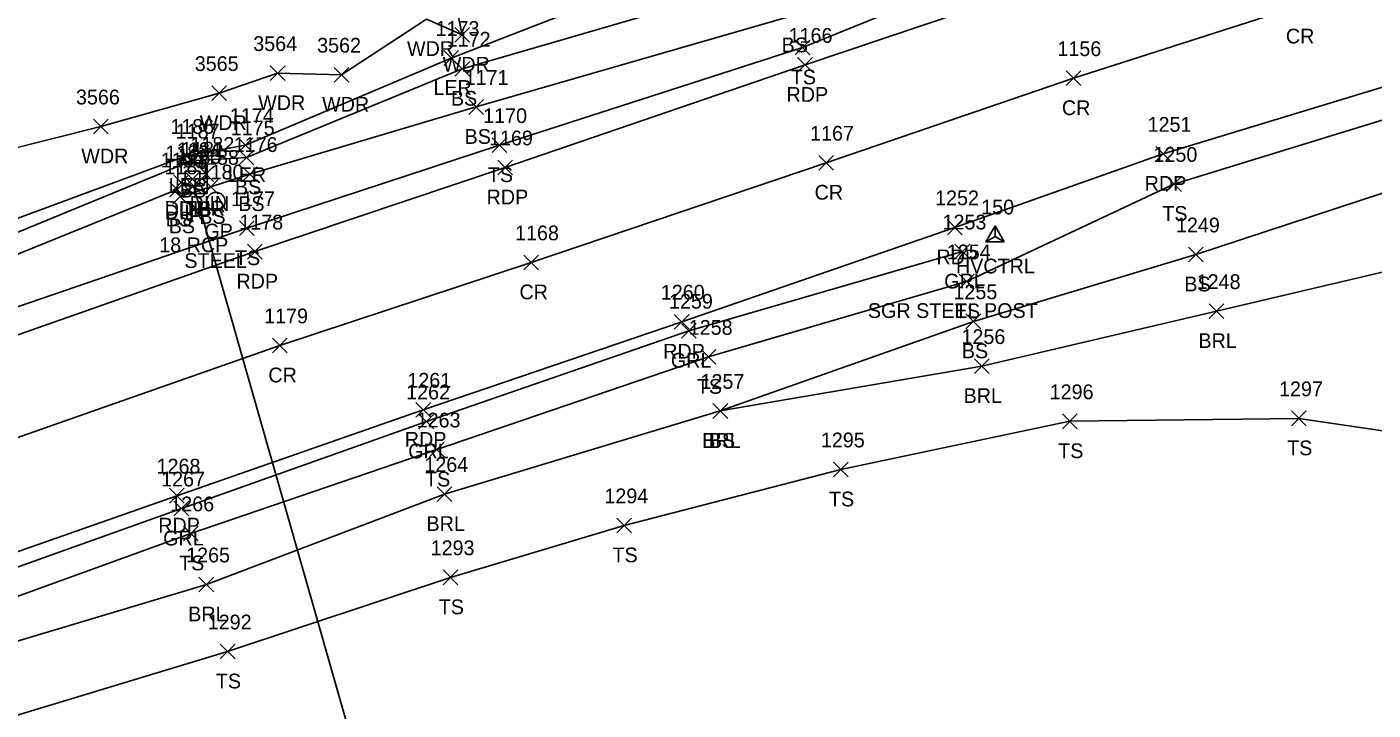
# Model space of a CAD drawing. Extents: x 1599569 to 1610055, y 642560 to 647860.
# Drawn here: x 1602081.3 to 1602263.8, y 647397.5 to 647490.2 of the extents above; entities that cross this region are included whole.
import ezdxf

# ---------------------------------------------------------------- set-up
doc = ezdxf.new("R2010")
doc.units = 0
for name, color, linetype in [('C_A', 7, 'Continuous'), ('C_I', 7, 'Continuous'), ('CPSM', 7, 'Continuous'), ('D_A', 7, 'Continuous'), ('D_C', 7, 'Continuous'), ('D_I', 7, 'Continuous'), ('D_TIC', 7, 'Continuous'), ('DCP', 7, 'Continuous'), ('DS', 7, 'Continuous'), ('L_A', 7, 'Continuous'), ('L_I', 7, 'Continuous'), ('L_TIC', 7, 'Continuous'), ('LABL', 7, 'Continuous'), ('LARO', 7, 'Continuous'), ('LAWA', 7, 'Continuous'), ('LELB', 7, 'Continuous'), ('P_A', 7, 'Continuous'), ('P_I', 7, 'Continuous'), ('P_TIC', 7, 'Continuous'), ('PET', 7, 'Continuous'), ('PRC', 7, 'Continuous'), ('R_A', 7, 'Continuous'), ('R_C', 7, 'Continuous'), ('R_I', 7, 'Continuous'), ('R_TIC', 7, 'Continuous'), ('RGP', 7, 'Continuous'), ('RGR', 7, 'Continuous')]:
    doc.layers.add(name, color=color, linetype=linetype)

msp = doc.modelspace()

# ---------------------------------------------------------------- linework, layer by layer
at = {"layer": 'CPSM'}
for p, q in [((1602211.32, 647461.02), (1602212.57, 647463.19)), ((1602213.82, 647461.02), (1602212.57, 647463.19)), ((1602212.57, 647461.74), (1602212.57, 647463.19)), ((1602211.32, 647461.02), (1602212.57, 647461.74)), ((1602211.32, 647461.02), (1602213.82, 647461.02)), ((1602212.57, 647461.74), (1602212.57, 647461.74)), ((1602212.57, 647461.74), (1602213.82, 647461.02))]:
    msp.add_line(p, q, dxfattribs=at)
at = {"layer": 'D_TIC'}
for points in [[(1602104.56, 647469.22), (1602106.56, 647471.22)], [(1602106.56, 647469.22), (1602104.56, 647471.22)], [(1602101.16, 647468.07), (1602103.16, 647470.07)], [(1602103.16, 647468.07), (1602101.16, 647470.07)], [(1602102.72, 647468.51), (1602104.72, 647470.51)], [(1602104.72, 647468.51), (1602102.72, 647470.51)], [(1602102.84, 647467.61), (1602104.84, 647469.61)], [(1602104.84, 647467.61), (1602102.84, 647469.61)]]:
    msp.add_lwpolyline(points, dxfattribs=at)
at = {"layer": 'DCP'}
msp.add_lwpolyline([(1602103.84, 647468.61), (1602127.27, 647386.57)], dxfattribs=at)
at = {"layer": 'DS'}
for p, q in [((1602101.7, 647471.59), (1602105.7, 647471.59)), ((1602101.7, 647467.59), (1602101.71, 647471.59)), ((1602105.7, 647471.59), (1602105.7, 647467.59)), ((1602102.7, 647470.59), (1602104.7, 647470.59)), ((1602102.7, 647468.59), (1602102.7, 647470.59)), ((1602103.7, 647469.6), (1602103.7, 647469.6)), ((1602104.7, 647470.59), (1602104.7, 647468.59)), ((1602105.7, 647467.59), (1602101.7, 647467.59)), ((1602104.7, 647468.59), (1602102.7, 647468.59)), ((1602104.2, 647467.59), (1602104.7, 647467.59))]:
    msp.add_line(p, q, dxfattribs=at)
at = {"layer": 'L_TIC'}
for points in [[(1602139.29, 647488.09), (1602141.29, 647490.09)], [(1602141.29, 647488.09), (1602139.29, 647490.09)], [(1602185.45, 647486.37), (1602187.45, 647488.37)], [(1602187.45, 647486.37), (1602185.45, 647488.37)], [(1602137.81, 647484.94), (1602139.81, 647486.94)], [(1602139.81, 647484.94), (1602137.81, 647486.94)], [(1602114.26, 647482.89), (1602116.26, 647484.89)], [(1602116.26, 647482.89), (1602114.26, 647484.89)], [(1602122.93, 647482.67), (1602124.93, 647484.67)], [(1602124.93, 647482.67), (1602122.93, 647484.67)], [(1602139.31, 647483.48), (1602141.31, 647485.48)], [(1602141.31, 647483.48), (1602139.31, 647485.48)], [(1602106.33, 647480.18), (1602108.33, 647482.18)], [(1602108.33, 647480.18), (1602106.33, 647482.18)], [(1602141.18, 647478.3), (1602143.18, 647480.3)], [(1602143.18, 647478.3), (1602141.18, 647480.3)], [(1602090.27, 647475.65), (1602092.27, 647477.65)], [(1602092.27, 647475.65), (1602090.27, 647477.65)], [(1602109.91, 647473.13), (1602111.91, 647475.13)], [(1602111.91, 647473.13), (1602109.91, 647475.13)], [(1602144.36, 647473.12), (1602146.36, 647475.12)], [(1602146.36, 647473.12), (1602144.36, 647475.12)], [(1602101.89, 647471.66), (1602103.89, 647473.66)], [(1602103.89, 647471.66), (1602101.89, 647473.66)], [(1602102.56, 647471.02), (1602104.56, 647473.02)], [(1602104.56, 647471.02), (1602102.56, 647473.02)], [(1602110.03, 647471.46), (1602112.03, 647473.46)], [(1602112.03, 647471.46), (1602110.03, 647473.46)], [(1602110.48, 647469.2), (1602112.48, 647471.2)], [(1602112.48, 647469.2), (1602110.48, 647471.2)], [(1602105.19, 647467.46), (1602107.19, 647469.46)], [(1602107.19, 647467.46), (1602105.19, 647469.46)], [(1602235.83, 647467.86), (1602237.83, 647469.86)], [(1602237.83, 647467.86), (1602235.83, 647469.86)], [(1602100.62, 647467.1), (1602102.62, 647469.1)], [(1602102.62, 647467.1), (1602100.62, 647469.1)], [(1602101.05, 647466.18), (1602103.05, 647468.18)], [(1602103.05, 647466.18), (1602101.05, 647468.18)], [(1602110.07, 647461.86), (1602112.07, 647463.86)], [(1602112.07, 647461.86), (1602110.07, 647463.86)], [(1602238.8, 647458.3), (1602240.8, 647460.3)], [(1602240.8, 647458.3), (1602238.8, 647460.3)], [(1602207.71, 647454.65), (1602209.71, 647456.65)], [(1602209.71, 647454.65), (1602207.71, 647456.65)], [(1602208.62, 647449.24), (1602210.62, 647451.24)], [(1602210.62, 647449.24), (1602208.62, 647451.24)], [(1602241.61, 647450.62), (1602243.61, 647452.62)], [(1602243.61, 647450.62), (1602241.61, 647452.62)], [(1602172.71, 647444.42), (1602174.71, 647446.42)], [(1602174.71, 647444.42), (1602172.71, 647446.42)], [(1602209.76, 647443.17), (1602211.76, 647445.17)], [(1602211.76, 647443.17), (1602209.76, 647445.17)], [(1602174.3, 647437.09), (1602176.3, 647439.09)], [(1602176.3, 647437.09), (1602174.3, 647439.09)], [(1602174.3, 647437.09), (1602176.3, 647439.09)], [(1602176.3, 647437.09), (1602174.3, 647439.09)], [(1602221.72, 647435.69), (1602223.72, 647437.69)], [(1602223.72, 647435.69), (1602221.72, 647437.69)], [(1602252.77, 647436.09), (1602254.77, 647438.09)], [(1602254.77, 647436.09), (1602252.77, 647438.09)], [(1602135.85, 647431.86), (1602137.85, 647433.86)], [(1602137.85, 647431.86), (1602135.85, 647433.86)], [(1602190.63, 647429.16), (1602192.63, 647431.16)], [(1602192.63, 647429.16), (1602190.63, 647431.16)], [(1602136.9, 647425.83), (1602138.9, 647427.83)], [(1602138.9, 647425.83), (1602136.9, 647427.83)], [(1602161.27, 647421.58), (1602163.27, 647423.58)], [(1602163.27, 647421.58), (1602161.27, 647423.58)], [(1602102.5, 647420.49), (1602104.5, 647422.49)], [(1602104.5, 647420.49), (1602102.5, 647422.49)], [(1602137.7, 647414.54), (1602139.7, 647416.54)], [(1602139.7, 647414.54), (1602137.7, 647416.54)], [(1602104.59, 647413.57), (1602106.59, 647415.57)], [(1602106.59, 647413.57), (1602104.59, 647415.57)], [(1602107.48, 647404.48), (1602109.48, 647406.48)], [(1602109.48, 647404.48), (1602107.48, 647406.48)]]:
    msp.add_lwpolyline(points, dxfattribs=at)
at = {"layer": 'LABL'}
msp.add_lwpolyline([(1602538.93, 647499.63), (1602515.77, 647504.47), (1602496.79, 647503.69), (1602468.13, 647504.07), (1602437.38, 647499.25), (1602407.68, 647491.96), (1602380.84, 647484.75), (1602352.64, 647480.69), (1602316.1, 647467.92), (1602276.24, 647459.53), (1602242.61, 647451.62), (1602210.76, 647444.17), (1602175.3, 647438.09), (1602137.9, 647426.83), (1602105.59, 647414.57), (1602070.4, 647404.05), (1602026.56, 647383.89), (1602007.33, 647369.55), (1602002.68, 647344.03), (1602051.38, 647339.86)], dxfattribs=at)
at = {"layer": 'LARO'}
msp.add_lwpolyline([(1602281.17, 647528.1), (1602249.28, 647518.68), (1602215.29, 647506.81), (1602182.96, 647503.09), (1602138.81, 647485.94), (1602110.91, 647474.13), (1602102.89, 647472.66), (1602065.84, 647459), (1602030.57, 647446.06), (1601996.63, 647434.93), (1601966.44, 647449.06), (1601954.75, 647432.61), (1601939.14, 647421.32), (1601907.5, 647403.47), (1601898.14, 647399.78), (1601888.11, 647399.67), (1601874.07, 647394.79), (1601848.49, 647386.96)], dxfattribs=at)
at = {"layer": 'LAWA'}
msp.add_lwpolyline([(1602267.89, 647531.91), (1602252.89, 647527.89), (1602245.34, 647522.06), (1602238.82, 647521.29), (1602231.93, 647518.02), (1602223.42, 647517.25), (1602221.44, 647514.34), (1602210.26, 647512.11), (1602187.69, 647505.07), (1602172.23, 647505.3), (1602151.88, 647506.59), (1602137.86, 647500.8), (1602140.29, 647489.09), (1602135.45, 647491.22), (1602123.93, 647483.67), (1602115.26, 647483.89), (1602107.33, 647481.18), (1602091.27, 647476.65), (1602071.28, 647471.64)], dxfattribs=at)
at = {"layer": 'LELB'}
for points in [[(1602281.75, 647527.04), (1602249.8, 647516.84), (1602215.67, 647505.92), (1602184.38, 647497.32), (1602140.31, 647484.48), (1602111.03, 647472.46), (1602103.56, 647472.02), (1602066.93, 647456.96), (1602030.71, 647444.95), (1601997.32, 647432.85), (1601974.14, 647429.14), (1601941.15, 647416.78), (1601908.35, 647402.2), (1601898.71, 647398.5), (1601889.19, 647398.4), (1601875.8, 647390.82), (1601849.76, 647382.4), (1601821.01, 647371.25), (1601793.34, 647364.77), (1601777.94, 647362.34), (1601752.2, 647359.53), (1601736.48, 647357.95), (1601705.98, 647345.02)], [(1602280.55, 647523.47), (1602249.62, 647512.84), (1602216.53, 647503.11), (1602185.17, 647491.71), (1602142.18, 647479.3), (1602111.48, 647470.2), (1602106.19, 647468.46), (1602102.05, 647467.18), (1602101.62, 647468.1), (1602067.36, 647454.23), (1602033.18, 647442.57), (1601998.29, 647429.71), (1601975.48, 647422.42), (1601942.86, 647410.81), (1601909.09, 647400.02), (1601898.83, 647395.63), (1601887.98, 647393.87), (1601875.49, 647387.75), (1601851.11, 647380.46), (1601821.5, 647369.32), (1601787.55, 647360.24), (1601760.01, 647349.17)], [(1602281.6, 647518.52), (1602249.84, 647509.15), (1602217.8, 647500.07), (1602186.45, 647487.37), (1602145.36, 647474.12), (1602111.07, 647462.86), (1602069.25, 647448.56), (1602037.69, 647438.14), (1601999.72, 647424.13), (1601976.97, 647416.76)], [(1602437.38, 647499.25), (1602407.74, 647500.37), (1602379.76, 647494.45), (1602350.6, 647487.83), (1602312.09, 647479.12), (1602274.73, 647470.77), (1602239.8, 647459.3), (1602209.62, 647450.24), (1602175.3, 647438.09)], [(1601875.37, 647298.23), (1601899.27, 647311.46), (1601933.4, 647328.44), (1601966.96, 647349.6), (1601991.6, 647361.72), (1602007.33, 647369.55), (1602053.05, 647388.73), (1602108.48, 647405.48), (1602138.7, 647415.54), (1602162.27, 647422.58), (1602191.63, 647430.16), (1602222.72, 647436.69), (1602253.77, 647437.09), (1602274.71, 647434), (1602308.64, 647432.46), (1602335.54, 647436.29), (1602372.31, 647451.76), (1602413.17, 647464.59), (1602450.85, 647476.95), (1602485.79, 647485.59)], [(1602272.83, 647479.89), (1602236.83, 647468.86), (1602208.71, 647455.65), (1602173.71, 647445.42), (1602136.85, 647432.86), (1602103.5, 647421.49), (1602068.54, 647408.84), (1602020.23, 647391.97), (1601979.79, 647378.49), (1601945.53, 647366.37), (1601912.4, 647353.37), (1601880.28, 647341.06), (1601842.54, 647327.65), (1601807.18, 647318.11)]]:
    msp.add_lwpolyline(points, dxfattribs=at)
at = {"layer": 'P_TIC'}
for points in [[(1602185.79, 647484), (1602187.79, 647486)], [(1602187.79, 647484), (1602185.79, 647486)], [(1602222.2, 647482.2), (1602224.2, 647484.2)], [(1602224.2, 647482.2), (1602222.2, 647484.2)], [(1602234.37, 647471.94), (1602236.37, 647473.94)], [(1602236.37, 647471.94), (1602234.37, 647473.94)], [(1602145.11, 647470.1), (1602147.11, 647472.1)], [(1602147.11, 647470.1), (1602145.11, 647472.1)], [(1602188.65, 647470.74), (1602190.65, 647472.74)], [(1602190.65, 647470.74), (1602188.65, 647472.74)], [(1602206.12, 647461.98), (1602208.12, 647463.98)], [(1602208.12, 647461.98), (1602206.12, 647463.98)], [(1602111.18, 647458.69), (1602113.18, 647460.69)], [(1602113.18, 647458.69), (1602111.18, 647460.69)], [(1602148.63, 647457.23), (1602150.63, 647459.23)], [(1602150.63, 647457.23), (1602148.63, 647459.23)], [(1602169.06, 647449.19), (1602171.06, 647451.19)], [(1602171.06, 647449.19), (1602169.06, 647451.19)], [(1602114.56, 647445.97), (1602116.56, 647447.97)], [(1602116.56, 647445.97), (1602114.56, 647447.97)], [(1602134.02, 647437.25), (1602136.02, 647439.25)], [(1602136.02, 647437.25), (1602134.02, 647439.25)], [(1602100.58, 647425.61), (1602102.58, 647427.61)], [(1602102.58, 647425.61), (1602100.58, 647427.61)]]:
    msp.add_lwpolyline(points, dxfattribs=at)
at = {"layer": 'PET'}
for points in [[(1602282.38, 647515.6), (1602249.91, 647506.25), (1602218.97, 647495.88), (1602186.79, 647485), (1602146.11, 647471.1), (1602112.18, 647459.69), (1602070.34, 647445.01), (1602039.17, 647434.41), (1602000.82, 647421.21), (1601977.59, 647413.11)], [(1602272.4, 647484.22), (1602235.37, 647472.94), (1602207.12, 647462.98), (1602170.06, 647450.19), (1602135.02, 647438.25), (1602101.58, 647426.61), (1602066.23, 647414.21), (1602018.32, 647396.86), (1601978.91, 647383.06), (1601944.09, 647370.64), (1601909.28, 647358.43)]]:
    msp.add_lwpolyline(points, dxfattribs=at)
at = {"layer": 'PRC'}
msp.add_lwpolyline([(1602285.69, 647502.77), (1602253.57, 647492.91), (1602223.2, 647483.2), (1602189.65, 647471.74), (1602149.63, 647458.23), (1602115.56, 647446.97), (1602074.55, 647432.6), (1602043.17, 647422.05), (1602005, 647408.7), (1601983.17, 647400.81)], dxfattribs=at)
at = {"layer": 'R_TIC'}
for points in [[(1602207.13, 647458.7), (1602209.13, 647460.7)], [(1602209.13, 647458.7), (1602207.13, 647460.7)], [(1602170.04, 647447.96), (1602172.04, 647449.96)], [(1602172.04, 647447.96), (1602170.04, 647449.96)], [(1602134.43, 647435.66), (1602136.43, 647437.66)], [(1602136.43, 647435.66), (1602134.43, 647437.66)], [(1602101.2, 647423.86), (1602103.2, 647425.86)], [(1602103.2, 647423.86), (1602101.2, 647425.86)]]:
    msp.add_lwpolyline(points, dxfattribs=at)
at = {"layer": 'RGP'}
msp.add_line((1602106.89, 647466.48), (1602106.89, 647466.48), dxfattribs=at)
for radius in [1.25, 0.0833]:
    msp.add_circle((1602106.89, 647466.48), radius, dxfattribs=at)
at = {"layer": 'RGR'}
msp.add_lwpolyline([(1602208.13, 647459.7), (1602171.04, 647448.96), (1602135.43, 647436.66), (1602102.2, 647424.86), (1602066.88, 647412.28), (1602018.59, 647395.18), (1601979.38, 647381.34), (1601944.8, 647369.09), (1601909.85, 647356.68), (1601879.27, 647345.75), (1601839.66, 647331.85), (1601805.55, 647320.04)], dxfattribs=at)

# ---------------------------------------------------------------- texts
at = {"layer": 'C_A'}
msp.add_text('HVCTRL', height=2, dxfattribs=at).set_placement((1602207.26, 647456.74))
at = {"layer": 'C_I'}
msp.add_text('150', height=2, dxfattribs=at).set_placement((1602210.69, 647464.74))
at = {"layer": 'D_A'}
for s, p in [('DIIN', (1602099.93, 647464.07)), ('DITHR', (1602099.94, 647464.57)), ('DIB', (1602101.83, 647464.51)), ('P', (1602103.22, 647463.61)), ('DIIN', (1602103.33, 647465.22))]:
    msp.add_text(s, height=2, dxfattribs=at).set_placement(p)
at = {"layer": 'D_C'}
msp.add_text('18 RCP', height=2, dxfattribs=at).set_placement((1602099.2, 647459.61))
at = {"layer": 'D_I'}
for s, p in [('1182', (1602103.43, 647473.22)), ('1183', (1602100.03, 647472.07)), ('1184', (1602101.6, 647472.51)), ('1185', (1602101.71, 647471.61)), ('1181', (1602102.16, 647472.57))]:
    msp.add_text(s, height=2, dxfattribs=at).set_placement(p)
at = {"layer": 'L_A'}
for s, p in [('WDR', (1602132.81, 647486.22)), ('BS', (1602183.61, 647486.71)), ('WDR', (1602137.65, 647484.09)), ('TS', (1602184.86, 647482.37)), ('LER', (1602136.39, 647480.94)), ('WDR', (1602112.62, 647478.89)), ('WDR', (1602121.29, 647478.67)), ('BS', (1602138.76, 647479.48)), ('WDR', (1602104.69, 647476.18)), ('BS', (1602140.62, 647474.3)), ('WDR', (1602088.63, 647471.65)), ('LER', (1602108.49, 647469.13)), ('TS', (1602143.77, 647469.12)), ('LER', (1602100.48, 647467.66)), ('BS', (1602109.47, 647467.46)), ('BS', (1602102, 647467.02)), ('BS', (1602109.92, 647465.2)), ('TS', (1602235.24, 647463.86)), ('BS', (1602100.06, 647463.1)), ('BS', (1602100.49, 647462.18)), ('BS', (1602104.63, 647463.46)), ('TS', (1602109.48, 647457.86)), ('BS', (1602238.24, 647454.3)), ('TS', (1602207.12, 647450.65)), ('BS', (1602208.06, 647445.24)), ('BRL', (1602240.15, 647446.62)), ('TS', (1602172.12, 647440.42)), ('BRL', (1602208.3, 647439.17)), ('BRL', (1602172.84, 647433.09)), ('BS', (1602173.74, 647433.09)), ('TS', (1602221.13, 647431.69)), ('TS', (1602252.18, 647432.09)), ('TS', (1602135.26, 647427.86)), ('TS', (1602190.04, 647425.16)), ('BRL', (1602135.45, 647421.83)), ('TS', (1602101.9, 647416.49)), ('TS', (1602160.68, 647417.58)), ('BRL', (1602103.13, 647409.57)), ('TS', (1602137.11, 647410.54)), ('TS', (1602106.88, 647400.48))]:
    msp.add_text(s, height=2, dxfattribs=at).set_placement(p)
at = {"layer": 'L_I'}
for s, p in [('1173', (1602136.68, 647488.94)), ('1172', (1602138.19, 647487.48)), ('3564', (1602111.95, 647486.89)), ('3562', (1602120.62, 647486.67)), ('3565', (1602104.02, 647484.18)), ('1171', (1602140.62, 647482.3)), ('3566', (1602087.91, 647479.65)), ('1174', (1602108.78, 647477.13)), ('1170', (1602143.14, 647477.12)), ('1186', (1602100.71, 647475.66)), ('1187', (1602101.43, 647475.02)), ('1175', (1602108.9, 647475.46)), ('1176', (1602109.3, 647473.2)), ('1190', (1602099.41, 647471.1)), ('1188', (1602104.06, 647471.46)), ('1250', (1602234.05, 647471.86)), ('1189', (1602099.91, 647470.18)), ('1177', (1602108.94, 647465.86)), ('1249', (1602237.1, 647462.3)), ('1254', (1602206.02, 647458.65)), ('1248', (1602239.91, 647454.62)), ('1255', (1602206.92, 647453.24)), ('1258', (1602171.02, 647448.42)), ('1256', (1602208.01, 647447.17)), ('1257', (1602172.61, 647441.09)), ('1257', (1602172.61, 647441.09)), ('1297', (1602251.08, 647440.09)), ('1296', (1602219.97, 647439.69)), ('1263', (1602134.11, 647435.86)), ('1295', (1602188.94, 647433.16)), ('1264', (1602135.16, 647429.83)), ('1294', (1602159.58, 647425.58)), ('1266', (1602100.7, 647424.49)), ('1293', (1602136.01, 647418.54)), ('1265', (1602102.85, 647417.57)), ('1292', (1602105.78, 647408.48))]:
    msp.add_text(s, height=2, dxfattribs=at).set_placement(p)
at = {"layer": 'P_A'}
for s, p in [('CR', (1602252.01, 647487.91)), ('RDP', (1602184.28, 647480)), ('CR', (1602221.63, 647478.2)), ('RDP', (1602232.86, 647467.94)), ('RDP', (1602143.6, 647466.1)), ('CR', (1602188.09, 647466.74)), ('RDP', (1602204.61, 647457.98)), ('RDP', (1602109.67, 647454.69)), ('CR', (1602148.06, 647453.23)), ('RDP', (1602167.55, 647445.19)), ('CR', (1602114, 647441.97)), ('RDP', (1602132.51, 647433.25)), ('RDP', (1602099.07, 647421.61))]:
    msp.add_text(s, height=2, dxfattribs=at).set_placement(p)
at = {"layer": 'P_I'}
for s, p in [('1166', (1602184.56, 647488)), ('1156', (1602221.02, 647486.2)), ('1167', (1602187.48, 647474.74)), ('1251', (1602233.25, 647475.94)), ('1169', (1602143.93, 647474.1)), ('1252', (1602204.43, 647465.98)), ('1178', (1602110.06, 647462.69)), ('1168', (1602147.46, 647461.23)), ('1260', (1602167.23, 647453.19)), ('1179', (1602113.43, 647449.97)), ('1261', (1602132.85, 647441.25)), ('1268', (1602098.84, 647429.61))]:
    msp.add_text(s, height=2, dxfattribs=at).set_placement(p)
at = {"layer": 'R_A'}
for s, p in [('GP', (1602105.32, 647461.48)), ('GRL', (1602205.67, 647454.7)), ('GRL', (1602168.59, 647443.96)), ('GRL', (1602132.97, 647431.66)), ('GRL', (1602099.74, 647419.86))]:
    msp.add_text(s, height=2, dxfattribs=at).set_placement(p)
at = {"layer": 'R_C'}
for s, p in [('STEEL', (1602102.61, 647457.48)), ('SGR STEEL POST', (1602195.32, 647450.7))]:
    msp.add_text(s, height=2, dxfattribs=at).set_placement(p)
at = {"layer": 'R_I'}
for s, p in [('1180', (1602104.68, 647469.48)), ('1253', (1602205.44, 647462.7)), ('1259', (1602168.34, 647451.96)), ('1262', (1602132.69, 647439.66)), ('1267', (1602099.46, 647427.86))]:
    msp.add_text(s, height=2, dxfattribs=at).set_placement(p)

doc.saveas('drawing.dxf')
